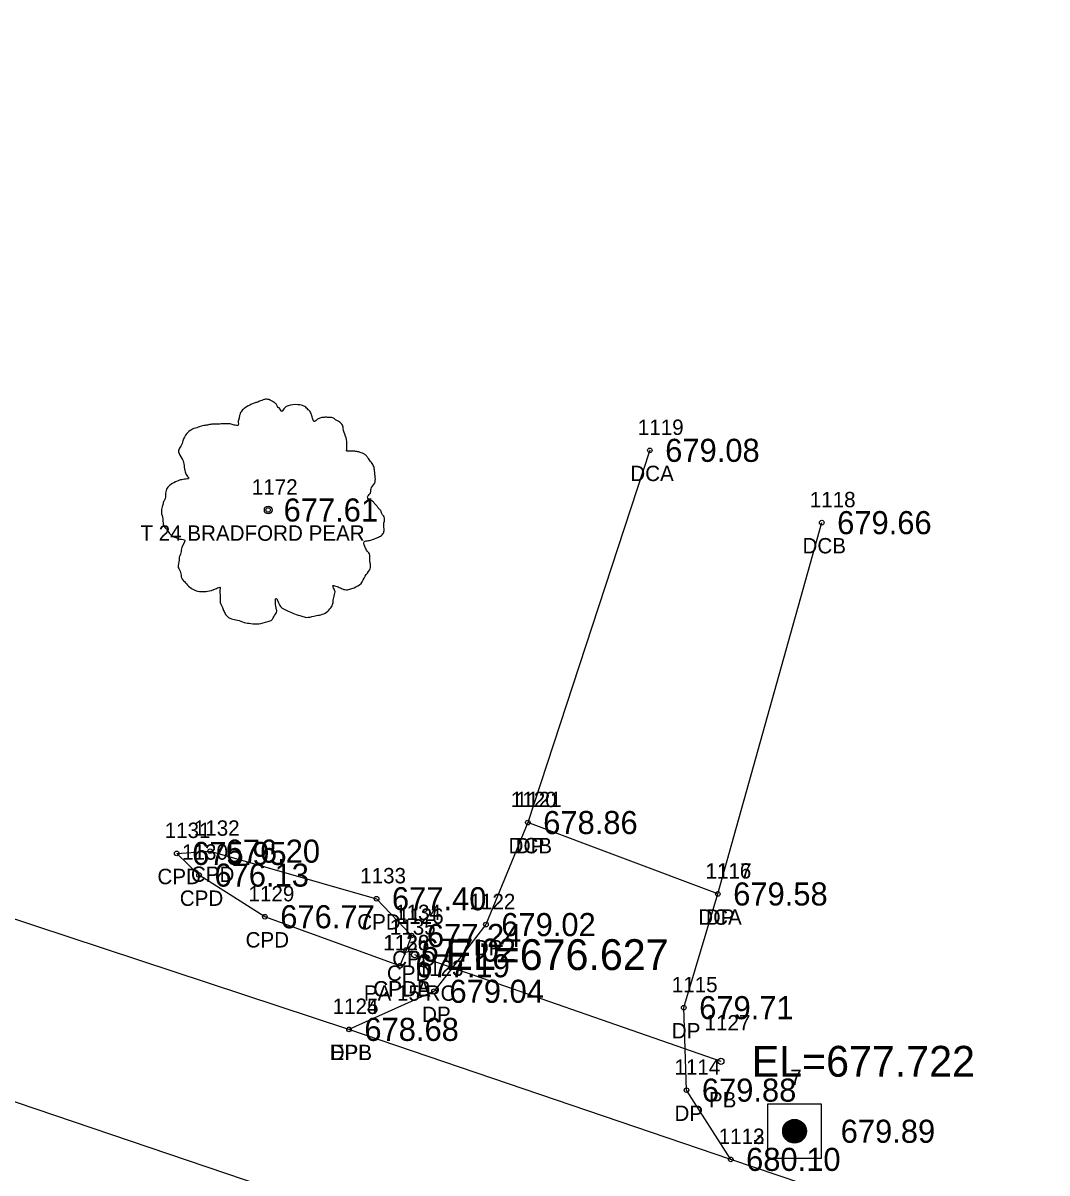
# Model space of a CAD drawing. Extents: x 1655137 to 1657928, y 1003994 to 1005407.
# Drawn here: x 1656780.6 to 1656847.1, y 1004485.2 to 1004559.9 of the extents above; entities that cross this region are included whole.
import ezdxf

# ---------------------------------------------------------------- set-up
doc = ezdxf.new("R2010")
doc.units = 0
for name, color, linetype in [('RD_EX_Conc', 7, 'Continuous'), ('RD_EX_Conc_txCode', 7, 'Continuous'), ('RD_EX_DR_Pipe', 7, 'Continuous'), ('RD_EX_DR_Pipe_txCode', 7, 'Continuous'), ('RD_EX_Driveway', 7, 'Continuous'), ('RD_EX_Driveway_txCode', 7, 'Continuous'), ('RD_EX_Road', 7, 'Continuous'), ('RD_EX_Road_txCode', 7, 'Continuous'), ('RD_EX_TX_Conc_ELEV', 7, 'Continuous'), ('RD_EX_TX_Driveway_ELEV', 7, 'Continuous'), ('RD_EX_TX_Road_ELEV', 7, 'Continuous'), ('RD_EX_TX_VEG_ELEV', 7, 'Continuous'), ('RD_EX_VEG', 7, 'Continuous'), ('RD_EX_VEG_txCode', 7, 'Continuous'), ('RD_HC_Cl', 7, 'Continuous'), ('RD_HC_Survey', 7, 'Continuous'), ('RD_HC_Survey_ELEV', 7, 'Continuous'), ('RD_HC_Survey_txCode', 7, 'Continuous'), ('RD_SMD_Locator', 7, 'Continuous'), ('RD_TX_Pipe_ElevEX', 7, 'Continuous')]:
    doc.layers.add(name, color=color, linetype=linetype)

msp = doc.modelspace()

# ---------------------------------------------------------------- linework, layer by layer
at = {"layer": 'RD_EX_Conc'}
for p, q in [((1656821.279, 1004532.136), (1656813.355, 1004507.948)), ((1656825.695, 1004503.307), (1656832.447, 1004527.437))]:
    msp.add_line(p, q, dxfattribs=at)
msp.add_lwpolyline([(1656805.052, 1004498.644), (1656796.277, 1004501.827), (1656792.003, 1004504.534), (1656790.551, 1004505.943), (1656792.725, 1004506.09), (1656803.53, 1004502.997), (1656805.8, 1004500.61), (1656805.457, 1004499.659), (1656805.052, 1004498.644)], dxfattribs=at)
at = {"layer": 'RD_EX_DR_Pipe'}
msp.add_line((1656805.998, 1004499.366), (1656825.896, 1004492.435), dxfattribs=at)
at = {"layer": 'RD_EX_Driveway'}
msp.add_lwpolyline([(1656826.533, 1004486.061), (1656823.66, 1004490.56), (1656823.485, 1004495.919), (1656825.695, 1004503.307), (1656813.355, 1004507.948), (1656810.632, 1004501.318), (1656807.267, 1004496.984), (1656801.74, 1004494.508)], dxfattribs=at)
at = {"layer": 'RD_EX_Road'}
msp.add_lwpolyline([(1657064.386, 1004409.093), (1657015.673, 1004424.638), (1656965.82, 1004440.601), (1656917.987, 1004455.951), (1656868.502, 1004471.858), (1656826.533, 1004486.061), (1656801.74, 1004494.508), (1656772.14, 1004504.273), (1656723.449, 1004520.924), (1656674.937, 1004537.34), (1656626.5, 1004553.879), (1656578.266, 1004569.524), (1656529.181, 1004584.752), (1656481.495, 1004600.509), (1656432.674, 1004617.136), (1656404.342, 1004625.816)], dxfattribs=at)
at = {"layer": 'RD_EX_VEG'}
for centre, radius in [((1656796.493, 1004528.259), 0.25), ((1656796.48, 1004528.24), 0.0001)]:
    msp.add_circle(centre, radius, dxfattribs=at)
for points in [[(1656796.625, 1004535.426), (1656796.325, 1004535.451), (1656796, 1004535.351), (1656795.75, 1004535.252), (1656795.525, 1004535.177), (1656795.3, 1004535.077), (1656795, 1004534.902), (1656794.776, 1004534.702), (1656794.651, 1004534.452), (1656794.601, 1004534.227), (1656794.551, 1004533.952), (1656794.551, 1004533.777), (1656794.426, 1004533.752), (1656794.276, 1004533.777), (1656794.026, 1004533.852), (1656793.776, 1004533.852), (1656793.526, 1004533.852), (1656793.176, 1004533.827), (1656792.826, 1004533.827), (1656792.552, 1004533.777), (1656792.227, 1004533.727), (1656791.852, 1004533.602), (1656791.502, 1004533.477), (1656791.202, 1004533.227), (1656790.952, 1004532.753), (1656790.827, 1004532.403), (1656790.677, 1004532.153), (1656790.827, 1004531.703), (1656791.002, 1004531.353), (1656791.027, 1004531.153), (1656791.102, 1004530.729), (1656791.202, 1004530.504), (1656791.327, 1004530.304), (1656791.252, 1004530.279), (1656790.877, 1004530.229), (1656790.577, 1004530.129), (1656790.153, 1004529.904), (1656789.928, 1004529.679), (1656789.828, 1004529.354), (1656789.803, 1004529.004), (1656789.703, 1004528.804), (1656789.628, 1004528.529), (1656789.603, 1004528.454), (1656789.553, 1004528.13), (1656789.653, 1004527.68), (1656789.678, 1004527.33), (1656789.803, 1004527.105), (1656789.953, 1004526.93), (1656790.128, 1004526.68), (1656790.527, 1004526.455), (1656790.852, 1004526.355), (1656791.052, 1004526.33), (1656790.877, 1004525.831), (1656790.827, 1004525.481), (1656790.702, 1004525.081), (1656790.702, 1004525.006), (1656790.652, 1004524.531), (1656790.802, 1004524.206), (1656790.877, 1004523.832), (1656791.052, 1004523.607), (1656791.327, 1004523.307), (1656791.652, 1004523.082), (1656792.152, 1004522.957), (1656792.552, 1004522.982), (1656793.126, 1004523.157), (1656793.376, 1004523.232), (1656793.351, 1004523.057), (1656793.376, 1004522.682), (1656793.376, 1004522.257), (1656793.526, 1004521.932), (1656793.626, 1004521.657), (1656793.776, 1004521.408), (1656794.101, 1004521.183), (1656794.501, 1004521.108), (1656794.925, 1004520.958), (1656795.375, 1004520.883), (1656795.875, 1004520.858), (1656796.475, 1004521.008), (1656796.75, 1004521.133), (1656796.85, 1004521.308), (1656797.05, 1004521.682), (1656797, 1004521.907), (1656797.025, 1004522.507), (1656797.124, 1004522.332), (1656797.299, 1004521.982), (1656797.799, 1004521.682), (1656798.199, 1004521.508), (1656798.674, 1004521.358), (1656798.974, 1004521.283), (1656799.448, 1004521.358), (1656799.823, 1004521.433), (1656800.198, 1004521.558), (1656800.498, 1004521.832), (1656800.673, 1004522.107), (1656800.723, 1004522.382), (1656800.798, 1004522.757), (1656800.848, 1004522.932)], [(1656800.848, 1004522.932), (1656800.773, 1004523.107), (1656800.723, 1004523.357), (1656800.798, 1004523.332), (1656800.973, 1004523.282), (1656801.248, 1004523.157), (1656801.473, 1004523.082), (1656801.797, 1004523.107), (1656802.072, 1004523.207), (1656802.522, 1004523.482), (1656802.797, 1004523.956), (1656803.072, 1004524.356), (1656803.147, 1004524.681), (1656803.097, 1004524.906), (1656803.072, 1004525.406), (1656802.872, 1004525.656), (1656802.822, 1004525.781), (1656802.722, 1004526.18), (1656802.797, 1004526.23), (1656803.072, 1004526.28), (1656803.447, 1004526.405), (1656803.722, 1004526.53), (1656803.947, 1004526.705), (1656804.021, 1004526.93), (1656803.997, 1004527.33), (1656804.046, 1004527.73), (1656803.972, 1004527.88), (1656803.872, 1004528.03), (1656803.797, 1004528.23), (1656803.647, 1004528.379), (1656803.547, 1004528.529), (1656803.447, 1004528.629), (1656803.322, 1004528.779), (1656803.147, 1004528.904), (1656802.997, 1004528.954), (1656802.947, 1004529.104), (1656803.097, 1004529.304), (1656803.147, 1004529.404), (1656803.172, 1004529.629), (1656803.397, 1004529.979), (1656803.447, 1004530.379), (1656803.397, 1004530.803), (1656803.347, 1004531.078), (1656803.197, 1004531.353), (1656802.997, 1004531.603), (1656802.872, 1004531.778), (1656802.697, 1004531.903), (1656802.372, 1004532.028), (1656802.122, 1004532.078), (1656801.772, 1004532.078), (1656801.573, 1004532.128), (1656801.598, 1004532.178), (1656801.598, 1004532.328), (1656801.598, 1004532.603), (1656801.523, 1004533.052), (1656801.373, 1004533.552), (1656801.373, 1004533.577), (1656801.273, 1004533.827), (1656801.048, 1004534.027), (1656800.873, 1004534.127), (1656800.673, 1004534.252), (1656800.423, 1004534.277), (1656800.123, 1004534.277), (1656799.848, 1004534.227), (1656799.648, 1004534.127), (1656799.473, 1004534.002), (1656799.398, 1004534.152), (1656799.299, 1004534.452), (1656799.249, 1004534.602), (1656799.099, 1004534.777), (1656798.874, 1004534.977), (1656798.424, 1004535.102), (1656797.799, 1004535.027), (1656797.499, 1004534.827), (1656797.349, 1004534.652), (1656797.299, 1004534.777), (1656797.099, 1004534.977), (1656797, 1004535.152), (1656796.825, 1004535.277), (1656796.675, 1004535.376), (1656796.575, 1004535.426)]]:
    msp.add_spline(points, degree=3, dxfattribs=at)
at = {"layer": 'RD_HC_Cl'}
msp.add_line((1656624.525, 1004542.444), (1656857.937, 1004463.429), dxfattribs=at)
at = {"layer": 'RD_HC_Survey'}
for p, q in [((1656830.424, 1004487.162), (1656830.424, 1004488.615)), ((1656830.448, 1004487.154), (1656830.448, 1004488.623)), ((1656830.473, 1004487.146), (1656830.473, 1004488.63)), ((1656830.498, 1004487.14), (1656830.498, 1004488.637)), ((1656830.523, 1004487.134), (1656830.523, 1004488.642)), ((1656830.547, 1004487.13), (1656830.547, 1004488.647)), ((1656830.572, 1004487.126), (1656830.572, 1004488.651)), ((1656830.597, 1004487.123), (1656830.597, 1004488.654)), ((1656830.622, 1004487.121), (1656830.622, 1004488.656)), ((1656830.646, 1004487.119), (1656830.646, 1004488.657)), ((1656830.671, 1004487.119), (1656830.671, 1004488.658)), ((1656830.696, 1004487.119), (1656830.696, 1004488.658)), ((1656830.721, 1004487.12), (1656830.721, 1004488.657)), ((1656830.745, 1004487.122), (1656830.745, 1004488.655)), ((1656830.77, 1004487.124), (1656830.77, 1004488.652)), ((1656830.795, 1004487.128), (1656830.795, 1004488.649)), ((1656830.82, 1004487.132), (1656830.82, 1004488.644)), ((1656830.844, 1004487.137), (1656830.844, 1004488.639)), ((1656830.869, 1004487.143), (1656830.869, 1004488.633)), ((1656830.894, 1004487.15), (1656830.894, 1004488.627)), ((1656830.919, 1004487.158), (1656830.919, 1004488.619)), ((1656829.929, 1004487.709), (1656829.929, 1004488.067)), ((1656829.954, 1004487.627), (1656829.954, 1004488.15)), ((1656829.978, 1004487.566), (1656829.978, 1004488.21)), ((1656830.003, 1004487.517), (1656830.003, 1004488.259)), ((1656830.028, 1004487.475), (1656830.028, 1004488.301)), ((1656830.052, 1004487.439), (1656830.052, 1004488.338)), ((1656830.077, 1004487.406), (1656830.077, 1004488.37)), ((1656830.102, 1004487.377), (1656830.102, 1004488.4)), ((1656830.127, 1004487.351), (1656830.127, 1004488.426)), ((1656830.151, 1004487.326), (1656830.151, 1004488.45)), ((1656830.176, 1004487.304), (1656830.176, 1004488.472)), ((1656830.201, 1004487.284), (1656830.201, 1004488.493)), ((1656830.226, 1004487.265), (1656830.226, 1004488.511)), ((1656830.25, 1004487.248), (1656830.25, 1004488.529)), ((1656830.275, 1004487.232), (1656830.275, 1004488.545)), ((1656830.3, 1004487.218), (1656830.3, 1004488.559)), ((1656830.325, 1004487.204), (1656830.325, 1004488.572)), ((1656830.349, 1004487.192), (1656830.349, 1004488.585)), ((1656830.374, 1004487.181), (1656830.374, 1004488.596)), ((1656830.399, 1004487.171), (1656830.399, 1004488.606)), ((1656830.943, 1004487.166), (1656830.943, 1004488.61)), ((1656830.968, 1004487.176), (1656830.968, 1004488.601)), ((1656830.993, 1004487.187), (1656830.993, 1004488.59)), ((1656831.018, 1004487.198), (1656831.018, 1004488.578)), ((1656831.042, 1004487.211), (1656831.042, 1004488.566)), ((1656831.067, 1004487.225), (1656831.067, 1004488.552)), ((1656831.092, 1004487.24), (1656831.092, 1004488.536)), ((1656831.117, 1004487.257), (1656831.117, 1004488.52)), ((1656831.141, 1004487.275), (1656831.141, 1004488.502)), ((1656831.166, 1004487.294), (1656831.166, 1004488.482)), ((1656831.191, 1004487.316), (1656831.191, 1004488.461)), ((1656831.216, 1004487.339), (1656831.216, 1004488.438)), ((1656831.24, 1004487.364), (1656831.24, 1004488.412)), ((1656831.265, 1004487.392), (1656831.265, 1004488.385)), ((1656831.29, 1004487.423), (1656831.29, 1004488.354)), ((1656831.315, 1004487.457), (1656831.315, 1004488.319)), ((1656831.339, 1004487.497), (1656831.339, 1004488.28)), ((1656831.364, 1004487.542), (1656831.364, 1004488.235)), ((1656831.389, 1004487.596), (1656831.389, 1004488.181)), ((1656831.414, 1004487.666), (1656831.414, 1004488.111)), ((1656831.438, 1004487.777), (1656831.438, 1004488))]:
    msp.add_line(p, q, dxfattribs=at)
msp.add_lwpolyline([(1656832.427, 1004489.638), (1656828.927, 1004489.638), (1656828.927, 1004486.138), (1656832.427, 1004486.138)], close=True, dxfattribs=at)
msp.add_circle((1656830.677, 1004487.888), 0.769, dxfattribs=at)
at = {"layer": 'RD_SMD_Locator'}
for centre, radius in [((1656821.279, 1004532.136), 0.15), ((1656796.493, 1004528.259), 0.15), ((1656832.447, 1004527.437), 0.15), ((1656813.355, 1004507.948), 0.15), ((1656813.355, 1004507.948), 0.15), ((1656790.551, 1004505.943), 0.15), ((1656792.725, 1004506.09), 0.15), ((1656792.003, 1004504.534), 0.15), ((1656803.53, 1004502.997), 0.15), ((1656825.695, 1004503.307), 0.15), ((1656825.695, 1004503.307), 0.15), ((1656796.277, 1004501.827), 0.15), ((1656810.632, 1004501.318), 0.15), ((1656805.8, 1004500.61), 0.15), ((1656805.457, 1004499.659), 0.15), ((1656805.998, 1004499.366), 0.2), ((1656805.052, 1004498.644), 0.15), ((1656805.052, 1004498.644), 0.15), ((1656807.267, 1004496.984), 0.15), ((1656823.485, 1004495.919), 0.15), ((1656801.74, 1004494.508), 0.15), ((1656801.74, 1004494.508), 0.15), ((1656825.896, 1004492.435), 0.2), ((1656823.66, 1004490.56), 0.15), ((1656830.677, 1004487.888), 0.15), ((1656826.533, 1004486.061), 0.15), ((1656826.533, 1004486.061), 0.15)]:
    msp.add_circle(centre, radius, dxfattribs=at)

# ---------------------------------------------------------------- texts
at = {"layer": 'RD_EX_Conc_txCode'}
for s, p in [('1119', (1656820.5, 1004533.136)), ('DCA', (1656820.012, 1004530.136)), ('1118', (1656831.667, 1004528.437)), ('DCB', (1656831.195, 1004525.437)), ('1120', (1656812.253, 1004508.948)), ('1132', (1656791.662, 1004507.09)), ('1131', (1656789.771, 1004506.943)), ('1130', (1656790.901, 1004505.534)), ('DCB', (1656812.103, 1004505.948)), ('CPD', (1656791.473, 1004504.09)), ('1117', (1656824.916, 1004504.307)), ('CPD', (1656789.299, 1004503.943)), ('1133', (1656802.467, 1004503.997)), ('1129', (1656795.214, 1004502.827)), ('CPD', (1656790.751, 1004502.534)), ('1134', (1656804.737, 1004501.61)), ('DCA', (1656824.427, 1004501.307)), ('CPD', (1656802.278, 1004500.997)), ('1135', (1656804.394, 1004500.659)), ('CPD', (1656795.025, 1004499.827)), ('1136', (1656803.966, 1004499.644)), ('1128', (1656803.989, 1004499.644)), ('CPD', (1656804.548, 1004498.61)), ('CPD', (1656804.205, 1004497.659)), ('CPDA', (1656803.312, 1004496.644)), ('CPDB', (1656803.328, 1004496.644))]:
    msp.add_text(s, height=1, dxfattribs=at).set_placement(p)
at = {"layer": 'RD_EX_DR_Pipe_txCode'}
for s, p in [('1126', (1656804.911, 1004501.366)), ('PA 15 RC', (1656802.706, 1004496.366)), ('1127', (1656824.833, 1004494.435)), ('PB', (1656825.116, 1004489.435))]:
    msp.add_text(s, height=1, dxfattribs=at).set_placement(p)
at = {"layer": 'RD_EX_Driveway_txCode'}
for s, p in [('1121', (1656812.575, 1004508.948)), ('DP', (1656812.575, 1004505.948)), ('1116', (1656824.892, 1004504.307)), ('1122', (1656809.569, 1004502.318)), ('DP', (1656824.916, 1004501.307)), ('DP', (1656809.852, 1004499.318)), ('1123', (1656806.204, 1004497.984)), ('1115', (1656822.705, 1004496.919)), ('1124', (1656800.677, 1004495.508)), ('DP', (1656806.487, 1004494.984)), ('DP', (1656822.705, 1004493.919)), ('DPB', (1656800.488, 1004492.508)), ('1114', (1656822.881, 1004491.56)), ('DP', (1656822.881, 1004488.56)), ('1113', (1656825.753, 1004487.061))]:
    msp.add_text(s, height=1, dxfattribs=at).set_placement(p)
at = {"layer": 'RD_EX_Road_txCode'}
for s, p in [('1125', (1656800.677, 1004495.508)), ('EPL', (1656800.536, 1004492.508)), ('1112', (1656825.753, 1004487.061))]:
    msp.add_text(s, height=1, dxfattribs=at).set_placement(p)
at = {"layer": 'RD_EX_TX_Conc_ELEV'}
for s, p in [('679.08', (1656822.279, 1004531.386)), ('679.66', (1656833.447, 1004526.687)), ('678.86', (1656814.355, 1004507.198)), ('675.95', (1656791.551, 1004505.193)), ('676.20', (1656793.725, 1004505.34)), ('676.13', (1656793.003, 1004503.784)), ('677.40', (1656804.53, 1004502.247)), ('679.58', (1656826.695, 1004502.557)), ('676.77', (1656797.277, 1004501.077)), ('677.24', (1656806.8, 1004499.86)), ('677.02', (1656806.457, 1004498.909)), ('677.19', (1656806.052, 1004497.894)), ('677.19', (1656806.052, 1004497.894))]:
    msp.add_text(s, height=1.5, dxfattribs=at).set_placement(p)
at = {"layer": 'RD_EX_TX_Driveway_ELEV'}
for s, p in [('678.86', (1656814.355, 1004507.198)), ('679.58', (1656826.695, 1004502.557)), ('679.02', (1656811.632, 1004500.568)), ('679.04', (1656808.267, 1004496.234)), ('679.71', (1656824.485, 1004495.169)), ('678.68', (1656802.74, 1004493.758)), ('679.88', (1656824.66, 1004489.81)), ('680.10', (1656827.533, 1004485.311))]:
    msp.add_text(s, height=1.5, dxfattribs=at).set_placement(p)
at = {"layer": 'RD_EX_TX_Road_ELEV'}
for s, p in [('678.68', (1656802.74, 1004493.758)), ('680.10', (1656827.533, 1004485.311))]:
    msp.add_text(s, height=1.5, dxfattribs=at).set_placement(p)
at = {"layer": 'RD_EX_TX_VEG_ELEV'}
msp.add_text('677.61', height=1.5, dxfattribs=at).set_placement((1656797.493, 1004527.509))
at = {"layer": 'RD_EX_VEG_txCode'}
for s, p in [('1172', (1656795.43, 1004529.259)), ('T 24 BRADFORD PEAR', (1656788.194, 1004526.259))]:
    msp.add_text(s, height=1, dxfattribs=at).set_placement(p)
at = {"layer": 'RD_HC_Survey_ELEV'}
msp.add_text('679.89', height=1.5, dxfattribs=at).set_placement((1656833.677, 1004487.138))
at = {"layer": 'RD_HC_Survey_txCode'}
msp.add_text('7', height=1, dxfattribs=at).set_placement((1656830.394, 1004490.888))
at = {"layer": 'RD_TX_Pipe_ElevEX'}
for s, p in [('EL=676.627', (1656807.998, 1004498.366)), ('EL=677.722', (1656827.896, 1004491.435))]:
    msp.add_text(s, height=2, dxfattribs=at).set_placement(p)

doc.saveas('drawing.dxf')
